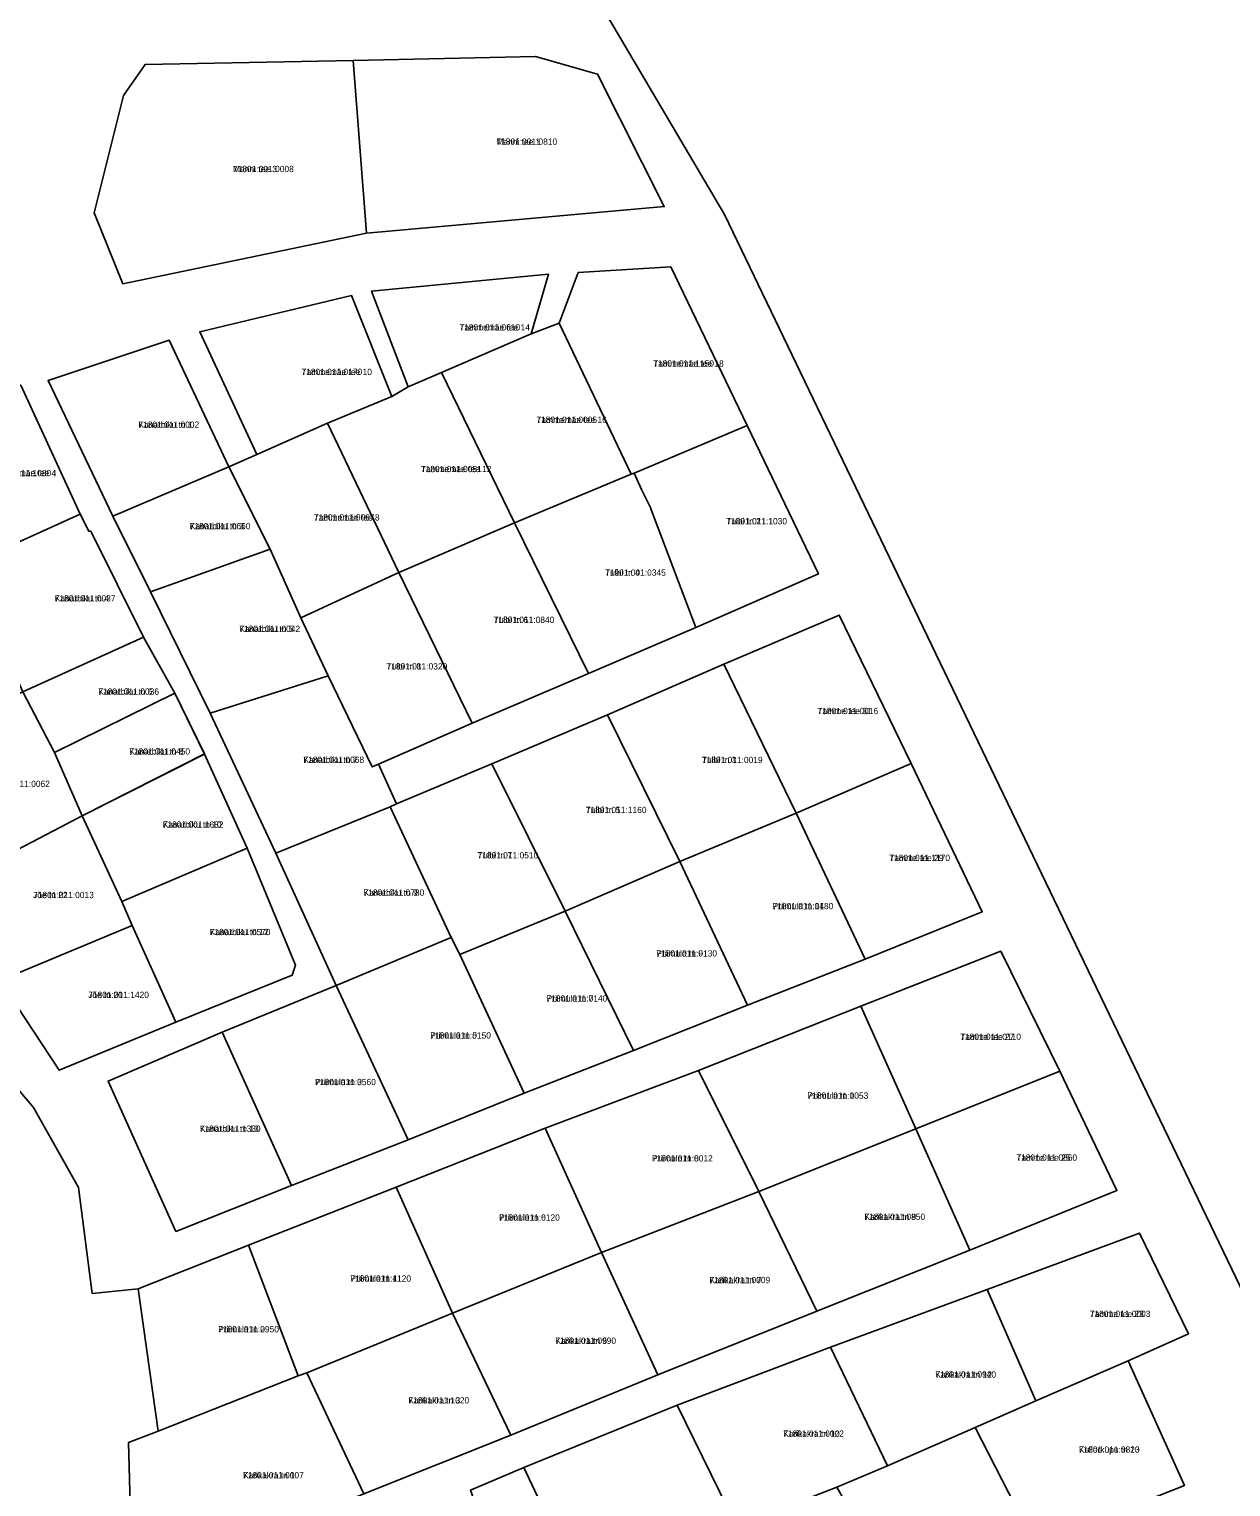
# Model space of a CAD drawing. Extents: x 529768 to 552006, y 6562269 to 6580975.
# Drawn here: x 537880.2 to 538167.2, y 6574791.4 to 6575139.4 of the extents above; entities that cross this region are included whole.
import ezdxf

# ---------------------------------------------------------------- set-up
doc = ezdxf.new("R2010")
doc.units = 0
for name, color, linetype in [('L_AADRESS', 7, 'Continuous'), ('PIIR', 7, 'Continuous'), ('TUNNUS', 7, 'Continuous')]:
    doc.layers.add(name, color=color, linetype=linetype)

msp = doc.modelspace()

# ---------------------------------------------------------------- linework, layer by layer
at = {"layer": 'PIIR'}
for points in [[(538180.52, 6574816.1), (538046.28, 6575095.15), (538015.03, 6575148.22), (537968.7, 6575245.88), (537953.95, 6575279.13), (537878.22, 6575434.31), (537836.88, 6575497.71), (537835.82, 6575499.74), (537814.57, 6575540.59), (537813.58, 6575542.49), (537936.83, 6575534.68), (538029.8, 6575526.57), (538029.63, 6575524.58), (538139.02, 6575510.04), (538242.97, 6575491.93)], [(537739.57, 6575152.36), (537752.93, 6575124.92), (537764.17, 6575098.61), (537787.43, 6575071.47), (537810.54, 6575042.33), (537804.89, 6575018.22), (537814.75, 6574987.16), (537827.97, 6574957.32), (537845.19, 6574925.01), (537861.18, 6574905.72), (537881.31, 6574881.94), (537891.99, 6574862.91), (537895.3, 6574837.6), (537906.26, 6574838.65), (537911.06, 6574804.7), (537903.95, 6574801.98), (537904.83, 6574769.93)], [(538015.03, 6575148.22), (538046.28, 6575095.15), (538180.52, 6574816.1)], [(537960.16, 6574789.77), (537995.22, 6574803.73), (538030.34, 6574818.13), (538068.29, 6574833.35), (538104.81, 6574847.88), (538139.96, 6574862.14), (538126.31, 6574890.66), (538112.24, 6574919.31), (538078.84, 6574906.2), (538040.07, 6574890.8), (538003.42, 6574877.07), (537967.84, 6574862.93), (537932.6, 6574849.09), (537906.26, 6574838.65), (537895.3, 6574837.6), (537891.99, 6574862.91), (537881.31, 6574881.94), (537861.18, 6574905.72)], [(538120.48, 6574777.61), (538156.07, 6574791.75), (538142.63, 6574821.49), (538157.04, 6574827.92), (538145.34, 6574851.98), (538108.96, 6574838.54), (538071.56, 6574824.72), (538034.99, 6574810.89), (537998.37, 6574795.99), (537985.66, 6574790.65)]]:
    msp.add_lwpolyline(points, dxfattribs=at)
for points in [[(537907.94, 6575130.95), (537902.79, 6575123.56), (537895.75, 6575095.58), (537902.61, 6575078.64), (537960.78, 6575090.74), (538031.89, 6575097.08), (538015.96, 6575128.64), (538001.18, 6575132.91), (537957.62, 6575131.94)], [(537960.78, 6575090.74), (537902.61, 6575078.64), (537895.75, 6575095.58), (537902.79, 6575123.56), (537907.94, 6575130.95), (537957.62, 6575131.94)], [(538001.18, 6575132.91), (538015.96, 6575128.64), (538031.89, 6575097.08), (537960.78, 6575090.74), (537957.62, 6575131.94)], [(537884.75, 6575055.58), (537900.19, 6575023.19), (537909.24, 6575005.12), (537923.48, 6574976.13), (537939.17, 6574942.68), (537953.54, 6574911.11), (537926.33, 6574899.95), (537899.09, 6574888.3), (537915.27, 6574852.4), (537942.91, 6574863.37), (537970.7, 6574874.25), (537998.45, 6574885.41), (538024.53, 6574895.61), (538051.8, 6574906.4), (538079.88, 6574917.42), (538107.83, 6574928.67), (538090.82, 6574964.14), (538073.65, 6574999.53), (538046.11, 6574987.79), (538018.31, 6574975.71), (537990.69, 6574964.02), (537967.97, 6574954.45), (537963.63, 6574963.93), (537986.04, 6574973.72), (538013.79, 6574985.61), (538039.41, 6574996.54), (538068.68, 6575009.36), (538051.7, 6575044.76), (538033.43, 6575082.65), (538011.36, 6575081.31), (538006.79, 6575069.24), (538000.09, 6575066.67), (538004.27, 6575080.91), (537962.02, 6575076.9), (537970.72, 6575054.05), (537966.81, 6575051.72), (537957.22, 6575075.83), (537920.97, 6575067.13), (537934.59, 6575037.87), (537927.93, 6575034.94), (537913.68, 6575065.14)], [(538006.79, 6575069.24), (538011.36, 6575081.31), (538033.43, 6575082.65), (538051.7, 6575044.76), (538024.71, 6575033.45), (538024, 6575033.16)], [(537970.72, 6575054.05), (537962.02, 6575076.9), (538004.27, 6575080.91), (538000.09, 6575066.67), (537978.67, 6575057.46)], [(537920.97, 6575067.13), (537957.22, 6575075.83), (537966.81, 6575051.72), (537951.47, 6575045.36), (537934.59, 6575037.87)], [(537978.67, 6575057.46), (538000.09, 6575066.67), (538006.79, 6575069.24), (538024, 6575033.16), (537996.12, 6575021.55)], [(537900.19, 6575023.19), (537884.75, 6575055.58), (537913.68, 6575065.14), (537927.93, 6575034.94)], [(537823.98, 6575027.38), (537838.08, 6574999.09), (537851.84, 6574969.13), (537847.37, 6574967.05), (537862.52, 6574935.76), (537859.04, 6574933.96), (537873.29, 6574912.33), (537887.42, 6574890.88), (537915.26, 6574902.32), (537943.04, 6574913.53), (537943.83, 6574915.98), (537932.32, 6574943.91), (537922.07, 6574966.37), (537915.04, 6574980.87), (537907.57, 6574994.3), (537894.96, 6575019.57), (537894.46, 6575019.54), (537892.46, 6575023.64), (537878.24, 6575054.44), (537849.52, 6575042.51), (537850.57, 6575040.41)], [(537849.52, 6575042.51), (537878.24, 6575054.44), (537892.46, 6575023.64), (537865.15, 6575011.33), (537850.57, 6575040.41)], [(537951.47, 6575045.36), (537966.81, 6575051.72), (537970.72, 6575054.05), (537978.67, 6575057.46), (537996.12, 6575021.55), (537968.49, 6575009.68)], [(537951.47, 6575045.36), (537968.49, 6575009.68), (537945.1, 6574998.88), (537937.77, 6575015.31), (537927.93, 6575034.94), (537934.59, 6575037.87)], [(538028.71, 6575024.92), (538028.66, 6575025.06), (538026.48, 6575029.49), (538024.71, 6575033.45), (538051.7, 6575044.76), (538068.68, 6575009.36), (538039.41, 6574996.54)], [(537900.19, 6575023.19), (537927.93, 6575034.94), (537937.77, 6575015.31), (537909.24, 6575005.12)], [(538013.79, 6574985.61), (537996.12, 6575021.55), (538024, 6575033.16), (538024.71, 6575033.45), (538026.48, 6575029.49), (538028.66, 6575025.06), (538028.71, 6575024.92), (538039.41, 6574996.54)], [(537865.15, 6575011.33), (537892.46, 6575023.64), (537894.46, 6575019.54), (537894.96, 6575019.57), (537907.57, 6574994.3), (537878.76, 6574981.24)], [(537968.49, 6575009.68), (537996.12, 6575021.55), (538013.79, 6574985.61), (537986.04, 6574973.72)], [(537909.24, 6575005.12), (537937.77, 6575015.31), (537945.1, 6574998.88), (537951.61, 6574985), (537923.48, 6574976.13)], [(537968.49, 6575009.68), (537986.04, 6574973.72), (537963.63, 6574963.93), (537962.17, 6574963.28), (537951.61, 6574985), (537945.1, 6574998.88)], [(538063.42, 6574952.28), (538046.11, 6574987.79), (538073.65, 6574999.53), (538090.82, 6574964.14)], [(537878.76, 6574981.24), (537907.57, 6574994.3), (537915.04, 6574980.87), (537886.29, 6574966.76)], [(537951.61, 6574985), (537962.17, 6574963.28), (537963.63, 6574963.93), (537967.97, 6574954.45), (537966.42, 6574953.79), (537939.17, 6574942.68), (537923.48, 6574976.13)], [(538063.42, 6574952.28), (538035.61, 6574940.69), (538018.31, 6574975.71), (538046.11, 6574987.79)], [(537878.76, 6574981.24), (537886.29, 6574966.76), (537892.86, 6574951.6), (537865.15, 6574937.12), (537862.52, 6574935.76), (537847.37, 6574967.05), (537851.84, 6574969.13)], [(537915.04, 6574980.87), (537922.09, 6574966.39), (537892.86, 6574951.6), (537886.29, 6574966.76)], [(537990.69, 6574964.02), (538018.31, 6574975.71), (538035.61, 6574940.69), (538008.19, 6574928.86)], [(537892.86, 6574951.6), (537922.07, 6574966.37), (537932.32, 6574943.91), (537902.36, 6574931.19)], [(537966.42, 6574953.79), (537967.97, 6574954.45), (537990.69, 6574964.02), (538008.19, 6574928.86), (537983.04, 6574918.53), (537981.01, 6574922.58)], [(538107.83, 6574928.67), (538079.88, 6574917.42), (538063.42, 6574952.28), (538090.82, 6574964.14)], [(537939.17, 6574942.68), (537966.42, 6574953.79), (537981.01, 6574922.58), (537953.54, 6574911.11)], [(537859.04, 6574933.96), (537862.52, 6574935.76), (537865.15, 6574937.12), (537892.86, 6574951.6), (537902.36, 6574931.19), (537904.81, 6574925.39), (537873.29, 6574912.33)], [(538051.8, 6574906.4), (538035.61, 6574940.69), (538063.42, 6574952.28), (538079.88, 6574917.42)], [(537902.36, 6574931.19), (537932.32, 6574943.91), (537943.82, 6574915.99), (537943.03, 6574913.53), (537915.26, 6574902.32), (537904.81, 6574925.39)], [(538024.53, 6574895.61), (538008.19, 6574928.86), (538035.61, 6574940.69), (538051.8, 6574906.4)], [(537998.45, 6574885.41), (537983.04, 6574918.53), (538008.19, 6574928.86), (538024.53, 6574895.61)], [(537873.29, 6574912.33), (537904.81, 6574925.39), (537915.26, 6574902.32), (537887.42, 6574890.88)], [(537970.7, 6574874.25), (537953.54, 6574911.11), (537981.01, 6574922.58), (537983.04, 6574918.53), (537998.45, 6574885.41)], [(538078.84, 6574906.2), (538112.24, 6574919.31), (538126.31, 6574890.66), (538091.99, 6574876.92)], [(537926.33, 6574899.95), (537953.54, 6574911.11), (537970.7, 6574874.25), (537942.91, 6574863.37)], [(538054.44, 6574861.92), (538040.07, 6574890.8), (538078.84, 6574906.2), (538091.99, 6574876.92)], [(537899.09, 6574888.3), (537926.33, 6574899.95), (537942.91, 6574863.37), (537915.27, 6574852.4)], [(538003.42, 6574877.07), (538040.07, 6574890.8), (538054.44, 6574861.92), (538016.93, 6574847.37)], [(538091.99, 6574876.92), (538126.31, 6574890.66), (538139.96, 6574862.14), (538104.81, 6574847.88)], [(537981.35, 6574832.85), (537967.84, 6574862.93), (538003.42, 6574877.07), (538016.93, 6574847.37)], [(538054.44, 6574861.92), (538091.99, 6574876.92), (538104.81, 6574847.88), (538068.29, 6574833.35)], [(537944.5, 6574817.88), (537932.6, 6574849.09), (537967.84, 6574862.93), (537981.35, 6574832.85), (537946.52, 6574818.64)], [(538054.44, 6574861.92), (538068.29, 6574833.35), (538030.34, 6574818.13), (538016.93, 6574847.37)], [(537906.26, 6574838.65), (537932.6, 6574849.09), (537944.5, 6574817.88), (537911.06, 6574804.7)], [(538108.96, 6574838.54), (538145.34, 6574851.98), (538157.04, 6574827.92), (538142.63, 6574821.49), (538120.62, 6574811.91)], [(537981.35, 6574832.85), (538016.93, 6574847.37), (538030.34, 6574818.13), (537995.22, 6574803.73)], [(538071.56, 6574824.72), (538108.96, 6574838.54), (538120.62, 6574811.91), (538106.12, 6574805.6), (538085.22, 6574796.45)], [(537946.52, 6574818.64), (537981.35, 6574832.85), (537995.22, 6574803.73), (537960.16, 6574789.77)], [(538085.22, 6574796.45), (538073.06, 6574791.35), (538049.15, 6574782), (538034.99, 6574810.89), (538071.56, 6574824.72)], [(538106.12, 6574805.6), (538120.62, 6574811.91), (538142.63, 6574821.49), (538156.07, 6574791.75), (538120.48, 6574777.61)], [(537960.16, 6574789.77), (537907.52, 6574768.22), (537904.83, 6574769.93), (537903.95, 6574801.98), (537911.06, 6574804.7), (537944.5, 6574817.88), (537946.52, 6574818.64)], [(538034.99, 6574810.89), (538049.15, 6574782), (538036.39, 6574776.37), (538012.14, 6574766.84), (537998.37, 6574795.99)], [(538088.44, 6574764.5), (538073.06, 6574791.35), (538085.22, 6574796.45), (538106.12, 6574805.6), (538120.48, 6574777.61)], [(537998.37, 6574795.99), (538012.14, 6574766.84), (537999.43, 6574761.17), (537996.55, 6574760.29), (537985.66, 6574790.65)]]:
    msp.add_lwpolyline(points, close=True, dxfattribs=at)

# ---------------------------------------------------------------- texts
at = {"layer": 'L_AADRESS'}
for s, p in [('Männi tee 1', (537991.81, 6575111.82)), ('Männi tee 3', (537928.93, 6575105.29)), ('Tammemäe tee 14', (537982.97, 6575067.48)), ('Tammemäe tee 10', (537945.26, 6575056.85)), ('Tammemäe tee 18', (538029.25, 6575058.87)), ('Kanarbiku tn 1', (537906.34, 6575044.25)), ('Tammemäe tee 16', (538001.34, 6575045.43)), ('Tammemäe tee 4', (537870.99, 6575032.7)), ('Tammemäe tee 12', (537973.79, 6575033.66)), ('Tammemäe tee 8', (537948.21, 6575022.11)), ('Kanarbiku tn 3', (537918.59, 6575020.03)), ('Tulbi tn 2', (538046.7, 6575021.2)), ('Tulbi tn 4', (538017.76, 6575008.93)), ('Kanarbiku tn 4', (537886.36, 6575002.79)), ('Tulbi tn 6', (537991.14, 6574997.66)), ('Kanarbiku tn 5', (537930.43, 6574995.5)), ('Tulbi tn 8', (537965.57, 6574986.55)), ('Kanarbiku tn 6', (537896.74, 6574980.53)), ('Tamme tee 31', (538068.46, 6574975.89)), ('Kanarbiku tn 8', (537904.15, 6574966.24)), ('Kanarbiku tn 7', (537945.72, 6574964.25)), ('Tulbi tn 3', (538040.87, 6574964.2)), ('Tulbi tn 5', (538013.15, 6574952.26)), ('Kanarbiku tn 10', (537912.14, 6574948.78)), ('Tulbi tn 7', (537987.3, 6574941.44)), ('Tamme tee 29', (538085.62, 6574940.81)), ('Jõe tn 22', (537881.18, 6574931.96)), ('Kanarbiku tn 9', (537960.09, 6574932.53)), ('Priimula tn 11', (538057.75, 6574929.32)), ('Kanarbiku tn 12', (537923.36, 6574923.12)), ('Priimula tn 9', (538029.99, 6574918.02)), ('Jõe tn 20', (537894.34, 6574908.13)), ('Priimula tn 7', (538003.79, 6574907.27)), ('Priimula tn 5', (537976, 6574898.43)), ('Tamme tee 27', (538102.56, 6574898.12)), ('Priimula tn 3', (537948.52, 6574887.31)), ('Priimula tn 10', (538066.1, 6574884.06)), ('Kanarbiku tn 13', (537921, 6574876.17)), ('Priimula tn 8', (538028.96, 6574869.09)), ('Tamme tee 25', (538115.96, 6574869.27)), ('Priimula tn 6', (537992.45, 6574854.96)), ('Karikakra tn 9', (538079.67, 6574855.14)), ('Priimula tn 4', (537956.93, 6574840.4)), ('Karikakra tn 7', (538042.68, 6574840.03)), ('Tamme tee 23', (538133.47, 6574831.95)), ('Priimula tn 2', (537925.38, 6574828.29)), ('Karikakra tn 5', (538005.88, 6574825.55)), ('Karikakra tn 12', (538096.61, 6574817.49)), ('Karikakra tn 3', (537970.8, 6574811.31)), ('Karikakra tn 10', (538060.28, 6574803.36)), ('Kullerkupu tn 13', (538130.88, 6574799.55)), ('Karikakra tn 1', (537931.31, 6574793.43))]:
    msp.add_text(s, height=1.5, dxfattribs=at).set_placement(p)
at = {"layer": 'TUNNUS'}
for s, p in [('71801:001:0810', (537991.81, 6575111.82)), ('71801:001:0008', (537928.93, 6575105.29)), ('71801:011:0610', (537982.97, 6575067.48)), ('71801:011:0170', (537945.26, 6575056.85)), ('71801:011:1150', (538029.25, 6575058.87)), ('71801:011:0002', (537906.34, 6575044.25)), ('71801:011:0005', (538001.34, 6575045.43)), ('71801:011:1080', (537870.99, 6575032.7)), ('71801:011:0051', (537973.79, 6575033.66)), ('71801:011:0067', (537948.21, 6575022.11)), ('71801:011:0660', (537918.59, 6575020.03)), ('71801:011:1030', (538046.7, 6575021.2)), ('71901:001:0345', (538017.76, 6575008.93)), ('71801:011:0037', (537886.36, 6575002.79)), ('71801:011:0840', (537991.14, 6574997.66)), ('71801:011:0042', (537930.43, 6574995.5)), ('71801:011:0320', (537965.57, 6574986.55)), ('71801:011:0036', (537896.74, 6574980.53)), ('71801:011:0016', (538068.46, 6574975.89)), ('71801:011:0450', (537904.15, 6574966.24)), ('71801:011:0068', (537945.72, 6574964.25)), ('71801:011:0019', (538040.87, 6574964.2)), ('71801:011:0062', (537870.69, 6574958.5)), ('71801:011:1160', (538013.15, 6574952.26)), ('71801:001:1682', (537912.14, 6574948.78)), ('71801:011:0510', (537987.3, 6574941.44)), ('71801:011:1170', (538085.62, 6574940.81)), ('71801:011:0013', (537881.18, 6574931.96)), ('71801:011:0780', (537960.09, 6574932.53)), ('71801:011:0480', (538057.75, 6574929.32)), ('71801:011:0570', (537923.36, 6574923.12)), ('71801:011:0130', (538029.99, 6574918.02)), ('71801:011:1420', (537894.34, 6574908.13)), ('71801:011:0140', (538003.79, 6574907.27)), ('71801:011:0150', (537976, 6574898.43)), ('71801:011:0110', (538102.56, 6574898.12)), ('71801:011:0560', (537948.52, 6574887.31)), ('71801:011:0053', (538066.1, 6574884.06)), ('71801:011:1330', (537921, 6574876.17)), ('71801:011:0012', (538028.96, 6574869.09)), ('71801:011:0860', (538115.96, 6574869.27)), ('71801:011:0120', (537992.45, 6574854.96)), ('71801:011:0850', (538079.67, 6574855.14)), ('71801:011:1120', (537956.93, 6574840.4)), ('71801:011:0009', (538042.68, 6574840.03)), ('71801:011:0003', (538133.47, 6574831.95)), ('71801:011:0950', (537925.38, 6574828.29)), ('71801:011:0990', (538005.88, 6574825.55)), ('71801:011:0940', (538096.61, 6574817.49)), ('71801:011:1020', (537970.8, 6574811.31)), ('71801:011:0022', (538060.28, 6574803.36)), ('71801:011:0820', (538130.88, 6574799.55)), ('71801:011:0007', (537931.31, 6574793.43))]:
    msp.add_text(s, height=1.5, dxfattribs=at).set_placement(p)

doc.saveas('drawing.dxf')
